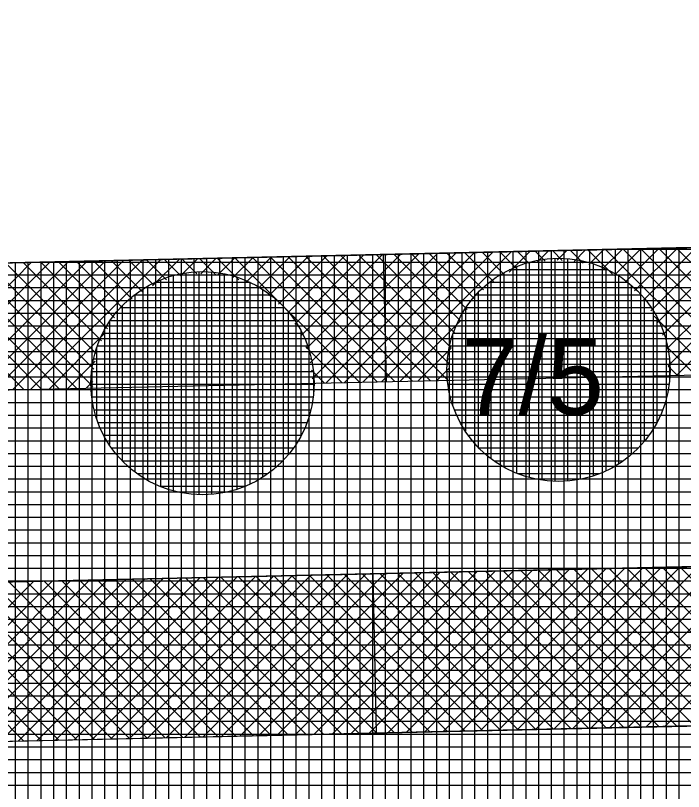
# Model space of a CAD drawing. Extents: x -566461 to -565198, y -1096301 to -1095707.
# Drawn here: x -565625.26 to -565614.79, y -1095879.91 to -1095867.74 of the extents above; entities that cross this region are included whole.
import ezdxf

# ---------------------------------------------------------------- set-up
doc = ezdxf.new("R2010")
doc.units = 0
for name, color, linetype in [('Vrstva 13', 7, 'Continuous'), ('Vrstva 40', 7, 'Continuous'), ('Vrstva 41', 7, 'Continuous'), ('Vrstva 42', 7, 'Continuous'), ('Vrstva 43', 7, 'Continuous'), ('Vrstva 44', 7, 'Continuous')]:
    doc.layers.add(name, color=color, linetype=linetype)

msp = doc.modelspace()

# ---------------------------------------------------------------- linework, layer by layer
at = {"layer": 'Vrstva 13'}
for p, q in [((-565630.22, -1095871.73), (-565610.5, -1095871.29)), ((-565630.41, -1095876.736), (-565610.165, -1095876.284)), ((-565630.354, -1095879.235), (-565610.109, -1095878.783))]:
    msp.add_line(p, q, dxfattribs=at)
at = {"layer": 'Vrstva 41'}
for p, q in [((-565615.422, -1095872.21), (-565614.593, -1095871.381)), ((-565615.303, -1095872.374), (-565614.304, -1095871.375)), ((-565615.201, -1095872.556), (-565614.014, -1095871.368)), ((-565615.119, -1095872.756), (-565613.725, -1095871.362)), ((-565615.062, -1095872.981), (-565613.436, -1095871.356)), ((-565615.033, -1095873.236), (-565613.146, -1095871.349)), ((-565614.901, -1095873.386), (-565612.857, -1095871.343)), ((-565621.004, -1095872.418), (-565620.09, -1095871.504)), ((-565620.885, -1095872.582), (-565619.8, -1095871.498)), ((-565620.783, -1095872.763), (-565619.511, -1095871.491)), ((-565620.7, -1095872.963), (-565619.222, -1095871.485)), ((-565620.642, -1095873.188), (-565618.932, -1095871.478)), ((-565620.614, -1095873.442), (-565618.643, -1095871.472)), ((-565620.393, -1095873.505), (-565618.354, -1095871.465)), ((-565618.465, -1095873.203), (-565620.162, -1095871.506)), ((-565620.104, -1095873.498), (-565618.065, -1095871.459)), ((-565618.434, -1095872.952), (-565619.886, -1095871.499)), ((-565619.815, -1095873.492), (-565617.775, -1095871.452)), ((-565618.372, -1095872.731), (-565619.609, -1095871.493)), ((-565619.526, -1095873.486), (-565617.486, -1095871.446)), ((-565618.287, -1095872.533), (-565619.332, -1095871.487)), ((-565618.184, -1095872.353), (-565619.056, -1095871.481)), ((-565618.062, -1095872.191), (-565618.779, -1095871.475)), ((-565617.925, -1095872.046), (-565618.502, -1095871.469)), ((-565617.772, -1095871.917), (-565618.226, -1095871.462)), ((-565617.6, -1095871.805), (-565617.949, -1095871.456)), ((-565617.409, -1095871.713), (-565617.672, -1095871.45)), ((-565617.523, -1095871.766), (-565617.197, -1095871.439)), ((-565617.198, -1095871.642), (-565617.396, -1095871.444)), ((-565616.962, -1095871.594), (-565617.119, -1095871.438)), ((-565617.089, -1095871.615), (-565616.907, -1095871.433)), ((-565616.691, -1095871.583), (-565616.842, -1095871.432)), ((-565616.773, -1095871.581), (-565616.618, -1095871.427)), ((-565616.366, -1095871.625), (-565616.566, -1095871.425)), ((-565616.508, -1095871.599), (-565616.329, -1095871.42)), ((-565615.907, -1095871.802), (-565616.289, -1095871.419)), ((-565616.275, -1095871.649), (-565616.039, -1095871.414)), ((-565616.066, -1095871.723), (-565615.75, -1095871.407)), ((-565614.058, -1095873.368), (-565616.012, -1095871.413)), ((-565615.878, -1095871.818), (-565615.461, -1095871.401)), ((-565613.781, -1095873.362), (-565615.736, -1095871.407)), ((-565615.709, -1095871.932), (-565615.172, -1095871.394)), ((-565615.558, -1095872.063), (-565614.882, -1095871.388)), ((-565613.681, -1095873.178), (-565615.459, -1095871.401)), ((-565613.658, -1095872.919), (-565615.182, -1095871.394)), ((-565613.605, -1095872.689), (-565614.906, -1095871.388)), ((-565626.13, -1095872.736), (-565625.008, -1095871.614)), ((-565626.04, -1095872.928), (-565624.718, -1095871.607)), ((-565625.97, -1095873.141), (-565624.429, -1095871.601)), ((-565625.925, -1095873.379), (-565624.14, -1095871.594)), ((-565625.886, -1095873.623), (-565623.85, -1095871.588)), ((-565625.597, -1095873.617), (-565623.561, -1095871.581)), ((-565623.986, -1095873.056), (-565625.419, -1095871.623)), ((-565625.308, -1095873.611), (-565623.272, -1095871.575)), ((-565623.914, -1095872.845), (-565625.142, -1095871.617)), ((-565625.019, -1095873.604), (-565622.983, -1095871.569)), ((-565623.821, -1095872.655), (-565624.866, -1095871.611)), ((-565623.709, -1095872.484), (-565624.589, -1095871.604)), ((-565623.58, -1095872.331), (-565624.312, -1095871.598)), ((-565623.434, -1095872.194), (-565624.036, -1095871.592)), ((-565623.271, -1095872.074), (-565623.759, -1095871.586)), ((-565623.092, -1095871.971), (-565623.482, -1095871.58)), ((-565622.893, -1095871.886), (-565623.206, -1095871.573)), ((-565623.113, -1095871.981), (-565622.693, -1095871.562)), ((-565622.671, -1095871.825), (-565622.929, -1095871.567)), ((-565622.674, -1095871.826), (-565622.404, -1095871.556)), ((-565622.419, -1095871.795), (-565622.652, -1095871.561)), ((-565622.127, -1095871.804), (-565622.376, -1095871.555)), ((-565622.357, -1095871.792), (-565622.115, -1095871.549)), ((-565621.758, -1095871.89), (-565622.099, -1095871.549)), ((-565622.092, -1095871.809), (-565621.825, -1095871.543)), ((-565621.858, -1095871.858), (-565621.536, -1095871.536)), ((-565619.872, -1095873.493), (-565621.822, -1095871.543)), ((-565621.649, -1095871.932), (-565621.247, -1095871.53)), ((-565619.595, -1095873.487), (-565621.546, -1095871.536)), ((-565621.461, -1095872.027), (-565620.958, -1095871.523)), ((-565621.292, -1095872.141), (-565620.668, -1095871.517)), ((-565619.318, -1095873.481), (-565621.269, -1095871.53)), ((-565621.14, -1095872.271), (-565620.379, -1095871.51)), ((-565619.041, -1095873.475), (-565620.992, -1095871.524)), ((-565618.764, -1095873.469), (-565620.716, -1095871.518)), ((-565618.487, -1095873.463), (-565620.439, -1095871.512)), ((-565625.132, -1095873.607), (-565627.079, -1095871.66)), ((-565624.855, -1095873.601), (-565626.802, -1095871.654)), ((-565624.578, -1095873.595), (-565626.526, -1095871.648)), ((-565624.302, -1095873.589), (-565626.249, -1095871.641)), ((-565624.047, -1095873.56), (-565625.972, -1095871.635)), ((-565624.034, -1095873.291), (-565625.696, -1095871.629)), ((-565614.334, -1095873.374), (-565615.252, -1095872.457)), ((-565619.237, -1095873.48), (-565618.284, -1095872.527)), ((-565624.729, -1095873.598), (-565623.859, -1095872.727)), ((-565620.149, -1095873.499), (-565620.71, -1095872.938)), ((-565618.948, -1095873.473), (-565618.435, -1095872.961)), ((-565614.611, -1095873.38), (-565615.075, -1095872.916)), ((-565624.44, -1095873.592), (-565624.014, -1095873.166)), ((-565620.425, -1095873.505), (-565620.624, -1095873.307)), ((-565618.659, -1095873.467), (-565618.469, -1095873.277)), ((-565614.888, -1095873.386), (-565615.033, -1095873.241)), ((-565624.151, -1095873.586), (-565624.048, -1095873.483)), ((-565616.528, -1095878.92), (-565613.977, -1095876.369)), ((-565616.238, -1095878.913), (-565613.688, -1095876.363)), ((-565615.949, -1095878.906), (-565613.399, -1095876.356)), ((-565615.66, -1095878.9), (-565613.11, -1095876.35)), ((-565615.37, -1095878.893), (-565612.82, -1095876.343)), ((-565615.081, -1095878.887), (-565612.531, -1095876.337)), ((-565622.027, -1095879.045), (-565619.474, -1095876.492)), ((-565621.738, -1095879.038), (-565619.185, -1095876.485)), ((-565621.448, -1095879.032), (-565618.896, -1095876.479)), ((-565621.159, -1095879.025), (-565618.606, -1095876.472)), ((-565620.87, -1095879.019), (-565618.317, -1095876.466)), ((-565620.58, -1095879.012), (-565618.028, -1095876.46)), ((-565620.291, -1095879.005), (-565617.738, -1095876.453)), ((-565620.001, -1095878.999), (-565617.449, -1095876.447)), ((-565619.712, -1095878.992), (-565617.16, -1095876.44)), ((-565617.113, -1095878.933), (-565619.553, -1095876.494)), ((-565619.422, -1095878.986), (-565616.87, -1095876.434)), ((-565616.837, -1095878.927), (-565619.276, -1095876.487)), ((-565619.133, -1095878.979), (-565616.581, -1095876.427)), ((-565616.56, -1095878.92), (-565618.999, -1095876.481)), ((-565618.843, -1095878.972), (-565616.292, -1095876.421)), ((-565616.284, -1095878.914), (-565618.723, -1095876.475)), ((-565618.554, -1095878.966), (-565616.003, -1095876.414)), ((-565616.007, -1095878.908), (-565618.446, -1095876.469)), ((-565618.265, -1095878.959), (-565615.713, -1095876.408)), ((-565615.731, -1095878.901), (-565618.169, -1095876.463)), ((-565617.975, -1095878.953), (-565615.424, -1095876.401)), ((-565615.454, -1095878.895), (-565617.893, -1095876.457)), ((-565617.686, -1095878.946), (-565615.135, -1095876.395)), ((-565615.178, -1095878.889), (-565617.616, -1095876.45)), ((-565617.396, -1095878.939), (-565614.845, -1095876.388)), ((-565614.901, -1095878.882), (-565617.339, -1095876.444)), ((-565617.107, -1095878.933), (-565614.556, -1095876.382)), ((-565614.625, -1095878.876), (-565617.063, -1095876.438)), ((-565616.817, -1095878.926), (-565614.267, -1095876.376)), ((-565614.348, -1095878.87), (-565616.786, -1095876.432)), ((-565614.072, -1095878.863), (-565616.509, -1095876.426)), ((-565613.795, -1095878.857), (-565616.233, -1095876.419)), ((-565613.518, -1095878.851), (-565615.956, -1095876.413)), ((-565613.242, -1095878.845), (-565615.679, -1095876.407)), ((-565612.965, -1095878.838), (-565615.403, -1095876.401)), ((-565612.689, -1095878.832), (-565615.126, -1095876.395)), ((-565612.412, -1095878.826), (-565614.849, -1095876.389)), ((-565627.527, -1095879.17), (-565624.971, -1095876.615)), ((-565627.237, -1095879.164), (-565624.682, -1095876.608)), ((-565626.948, -1095879.157), (-565624.392, -1095876.602)), ((-565626.659, -1095879.151), (-565624.103, -1095876.595)), ((-565626.369, -1095879.144), (-565623.814, -1095876.589)), ((-565626.08, -1095879.137), (-565623.524, -1095876.582)), ((-565625.79, -1095879.131), (-565623.235, -1095876.576)), ((-565625.501, -1095879.124), (-565622.946, -1095876.569)), ((-565625.211, -1095879.118), (-565622.656, -1095876.563)), ((-565624.922, -1095879.111), (-565622.367, -1095876.556)), ((-565622.368, -1095879.053), (-565624.809, -1095876.611)), ((-565624.632, -1095879.104), (-565622.078, -1095876.55)), ((-565622.091, -1095879.046), (-565624.533, -1095876.605)), ((-565624.343, -1095879.098), (-565621.789, -1095876.544)), ((-565621.814, -1095879.04), (-565624.256, -1095876.599)), ((-565624.053, -1095879.091), (-565621.499, -1095876.537)), ((-565621.538, -1095879.034), (-565623.979, -1095876.592)), ((-565623.764, -1095879.085), (-565621.21, -1095876.531)), ((-565621.261, -1095879.028), (-565623.703, -1095876.586)), ((-565623.475, -1095879.078), (-565620.921, -1095876.524)), ((-565620.985, -1095879.021), (-565623.426, -1095876.58)), ((-565623.185, -1095879.071), (-565620.631, -1095876.518)), ((-565620.708, -1095879.015), (-565623.149, -1095876.574)), ((-565622.896, -1095879.065), (-565620.342, -1095876.511)), ((-565620.432, -1095879.009), (-565622.873, -1095876.568)), ((-565622.606, -1095879.058), (-565620.053, -1095876.505)), ((-565620.155, -1095879.002), (-565622.596, -1095876.562)), ((-565619.879, -1095878.996), (-565622.319, -1095876.555)), ((-565622.317, -1095879.052), (-565619.763, -1095876.498)), ((-565619.602, -1095878.99), (-565622.043, -1095876.549)), ((-565619.326, -1095878.983), (-565621.766, -1095876.543)), ((-565619.049, -1095878.977), (-565621.489, -1095876.537)), ((-565618.773, -1095878.971), (-565621.213, -1095876.531)), ((-565618.496, -1095878.964), (-565620.936, -1095876.524)), ((-565618.22, -1095878.958), (-565620.659, -1095876.518)), ((-565617.943, -1095878.952), (-565620.383, -1095876.512)), ((-565617.666, -1095878.946), (-565620.106, -1095876.506)), ((-565617.39, -1095878.939), (-565619.829, -1095876.5)), ((-565625.133, -1095879.116), (-565627.576, -1095876.673)), ((-565624.856, -1095879.11), (-565627.299, -1095876.667)), ((-565624.58, -1095879.103), (-565627.023, -1095876.66)), ((-565624.303, -1095879.097), (-565626.746, -1095876.654)), ((-565624.027, -1095879.091), (-565626.469, -1095876.648)), ((-565623.75, -1095879.084), (-565626.193, -1095876.642)), ((-565623.474, -1095879.078), (-565625.916, -1095876.636)), ((-565623.197, -1095879.072), (-565625.639, -1095876.629)), ((-565622.921, -1095879.065), (-565625.363, -1095876.623)), ((-565622.644, -1095879.059), (-565625.086, -1095876.617))]:
    msp.add_line(p, q, dxfattribs=at)
at = {"layer": 'Vrstva 42'}
for p, q in [((-565619.498, -1095871.491), (-565619.453, -1095873.484)), ((-565619.663, -1095876.496), (-565619.607, -1095878.995))]:
    msp.add_line(p, q, dxfattribs=at)
for points in [[(-565642.21, -1095870.56), (-565642.251, -1095872.566), (-565630.414, -1095873.721), (-565610.455, -1095873.29), (-565587.747, -1095870.748), (-565569.297, -1095867.734), (-565519.622, -1095865.105), (-565519.36, -1095863.08), (-565569.62, -1095865.76), (-565587.97, -1095868.76), (-565610.5, -1095871.29), (-565630.22, -1095871.73)], [(-565642.542, -1095875.552), (-565642.365, -1095878.081), (-565630.354, -1095879.235), (-565609.886, -1095878.768), (-565587.002, -1095876.198), (-565568.675, -1095873.205), (-565520.341, -1095870.651), (-565520.014, -1095868.13), (-565569.078, -1095870.738), (-565587.281, -1095873.714), (-565610.165, -1095876.284), (-565630.41, -1095876.736)]]:
    msp.add_lwpolyline(points, close=True, dxfattribs=at)
at = {"layer": 'Vrstva 43'}
for p, q in [((-565620.06, -1095886.508), (-565620.06, -1095871.503)), ((-565619.86, -1095886.504), (-565619.86, -1095871.499)), ((-565619.66, -1095886.499), (-565619.66, -1095871.494)), ((-565619.46, -1095886.495), (-565619.46, -1095871.49)), ((-565619.26, -1095886.49), (-565619.26, -1095871.485)), ((-565619.06, -1095886.486), (-565619.06, -1095871.481)), ((-565618.86, -1095886.481), (-565618.86, -1095871.477)), ((-565618.66, -1095886.477), (-565618.66, -1095871.472)), ((-565618.46, -1095886.472), (-565618.46, -1095871.468)), ((-565618.26, -1095886.468), (-565618.26, -1095871.463)), ((-565618.06, -1095886.463), (-565618.06, -1095871.459)), ((-565617.86, -1095886.459), (-565617.86, -1095871.454)), ((-565617.66, -1095886.454), (-565617.66, -1095871.45)), ((-565617.46, -1095886.45), (-565617.46, -1095871.445)), ((-565617.26, -1095886.445), (-565617.26, -1095871.441)), ((-565617.06, -1095886.441), (-565617.06, -1095871.436)), ((-565616.86, -1095886.436), (-565616.86, -1095871.432)), ((-565616.66, -1095886.432), (-565616.66, -1095871.427)), ((-565616.46, -1095886.427), (-565616.46, -1095871.423)), ((-565616.26, -1095886.423), (-565616.26, -1095871.419)), ((-565616.06, -1095886.418), (-565616.06, -1095871.414)), ((-565615.878, -1095871.41), (-565520.439, -1095871.41)), ((-565615.86, -1095886.414), (-565615.86, -1095871.41)), ((-565615.66, -1095886.409), (-565615.66, -1095871.405)), ((-565615.46, -1095886.405), (-565615.46, -1095871.401)), ((-565615.26, -1095886.4), (-565615.26, -1095871.396)), ((-565615.06, -1095886.396), (-565615.06, -1095871.392)), ((-565614.86, -1095886.391), (-565614.86, -1095871.387)), ((-565625.26, -1095886.626), (-565625.26, -1095871.619)), ((-565625.06, -1095886.621), (-565625.06, -1095871.615)), ((-565624.86, -1095886.617), (-565624.86, -1095871.61)), ((-565624.842, -1095871.61), (-565520.465, -1095871.61)), ((-565624.66, -1095886.612), (-565624.66, -1095871.606)), ((-565624.46, -1095886.608), (-565624.46, -1095871.601)), ((-565624.26, -1095886.603), (-565624.26, -1095871.597)), ((-565624.06, -1095886.598), (-565624.06, -1095871.593)), ((-565623.86, -1095886.594), (-565623.86, -1095871.588)), ((-565623.66, -1095886.589), (-565623.66, -1095871.584)), ((-565623.46, -1095886.585), (-565623.46, -1095871.579)), ((-565623.26, -1095886.58), (-565623.26, -1095871.575)), ((-565623.06, -1095886.576), (-565623.06, -1095871.57)), ((-565622.86, -1095886.571), (-565622.86, -1095871.566)), ((-565622.66, -1095886.567), (-565622.66, -1095871.561)), ((-565622.46, -1095886.562), (-565622.46, -1095871.557)), ((-565622.26, -1095886.558), (-565622.26, -1095871.552)), ((-565622.06, -1095886.553), (-565622.06, -1095871.548)), ((-565621.86, -1095886.549), (-565621.86, -1095871.543)), ((-565621.66, -1095886.544), (-565621.66, -1095871.539)), ((-565621.46, -1095886.54), (-565621.46, -1095871.535)), ((-565621.26, -1095886.535), (-565621.26, -1095871.53)), ((-565621.06, -1095886.531), (-565621.06, -1095871.526)), ((-565620.86, -1095886.526), (-565620.86, -1095871.521)), ((-565620.66, -1095886.522), (-565620.66, -1095871.517)), ((-565620.46, -1095886.517), (-565620.46, -1095871.512)), ((-565620.26, -1095886.513), (-565620.26, -1095871.508)), ((-565642.236, -1095871.81), (-565520.491, -1095871.81)), ((-565642.24, -1095872.01), (-565520.517, -1095872.01)), ((-565642.244, -1095872.21), (-565520.543, -1095872.21)), ((-565642.248, -1095872.41), (-565520.569, -1095872.41)), ((-565642.252, -1095872.61), (-565520.595, -1095872.61)), ((-565642.256, -1095872.81), (-565520.62, -1095872.81)), ((-565642.26, -1095873.01), (-565520.646, -1095873.01)), ((-565642.265, -1095873.21), (-565520.672, -1095873.21)), ((-565642.269, -1095873.41), (-565520.698, -1095873.41)), ((-565642.273, -1095873.61), (-565520.724, -1095873.61)), ((-565642.277, -1095873.81), (-565520.75, -1095873.81)), ((-565642.281, -1095874.01), (-565520.776, -1095874.01)), ((-565642.285, -1095874.21), (-565520.802, -1095874.21)), ((-565642.289, -1095874.41), (-565520.828, -1095874.41)), ((-565642.293, -1095874.61), (-565520.854, -1095874.61)), ((-565642.298, -1095874.81), (-565520.88, -1095874.81)), ((-565642.302, -1095875.01), (-565520.905, -1095875.01)), ((-565642.306, -1095875.21), (-565520.931, -1095875.21)), ((-565642.31, -1095875.41), (-565520.957, -1095875.41)), ((-565642.314, -1095875.61), (-565520.983, -1095875.61)), ((-565642.318, -1095875.81), (-565521.009, -1095875.81)), ((-565642.322, -1095876.01), (-565521.035, -1095876.01)), ((-565642.326, -1095876.21), (-565521.061, -1095876.21)), ((-565642.331, -1095876.41), (-565521.087, -1095876.41)), ((-565642.335, -1095876.61), (-565521.113, -1095876.61)), ((-565642.339, -1095876.81), (-565521.139, -1095876.81)), ((-565642.343, -1095877.01), (-565521.165, -1095877.01)), ((-565642.347, -1095877.21), (-565521.19, -1095877.21)), ((-565642.351, -1095877.41), (-565521.216, -1095877.41)), ((-565642.355, -1095877.61), (-565521.242, -1095877.61)), ((-565642.359, -1095877.81), (-565521.268, -1095877.81)), ((-565642.364, -1095878.01), (-565521.294, -1095878.01)), ((-565642.368, -1095878.21), (-565521.32, -1095878.21)), ((-565642.372, -1095878.41), (-565525.085, -1095878.41)), ((-565642.376, -1095878.61), (-565528.851, -1095878.61)), ((-565642.38, -1095878.81), (-565532.616, -1095878.81)), ((-565642.384, -1095879.01), (-565536.381, -1095879.01)), ((-565642.388, -1095879.21), (-565540.147, -1095879.21)), ((-565642.392, -1095879.41), (-565543.912, -1095879.41)), ((-565642.397, -1095879.61), (-565547.677, -1095879.61)), ((-565642.401, -1095879.81), (-565551.443, -1095879.81))]:
    msp.add_line(p, q, dxfattribs=at)
msp.add_lwpolyline([(-565639.56, -1095885.89), (-565630.78, -1095886.75), (-565609.49, -1095886.27), (-565595.88, -1095884.74), (-565585.92, -1095883.62), (-565568.01, -1095880.69), (-565521.32, -1095878.21), (-565519.36, -1095863.08), (-565522.03, -1095863.23), (-565569.62, -1095865.76), (-565587.97, -1095868.76), (-565610.5, -1095871.29), (-565630.22, -1095871.73), (-565642.21, -1095870.56), (-565642.52, -1095885.6), (-565645.08, -1096008.78), (-565642.11, -1096010.51)], close=True, dxfattribs=at)
at = {"layer": 'Vrstva 44'}
for p, q in [((-565617.21, -1095871.612), (-565617.21, -1095874.988)), ((-565617.01, -1095871.571), (-565617.01, -1095875.029)), ((-565616.81, -1095871.553), (-565616.81, -1095875.048)), ((-565616.61, -1095871.557), (-565616.61, -1095875.043)), ((-565616.41, -1095871.584), (-565616.41, -1095875.015)), ((-565615.981, -1095871.73), (-565617.522, -1095871.73)), ((-565617.41, -1095871.681), (-565617.41, -1095874.92)), ((-565616.21, -1095871.636), (-565616.21, -1095874.963)), ((-565616.01, -1095871.716), (-565616.01, -1095874.885)), ((-565622.79, -1095871.822), (-565622.79, -1095875.198)), ((-565622.59, -1095871.781), (-565622.59, -1095875.239)), ((-565622.39, -1095871.763), (-565622.39, -1095875.258)), ((-565622.19, -1095871.767), (-565622.19, -1095875.253)), ((-565621.99, -1095871.794), (-565621.99, -1095875.225)), ((-565621.79, -1095871.846), (-565621.79, -1095875.173)), ((-565617.61, -1095871.778), (-565617.61, -1095874.822)), ((-565615.81, -1095871.825), (-565615.81, -1095874.774)), ((-565623.19, -1095871.988), (-565623.19, -1095875.032)), ((-565621.582, -1095871.93), (-565623.079, -1095871.93)), ((-565622.99, -1095871.891), (-565622.99, -1095875.13)), ((-565621.59, -1095871.926), (-565621.59, -1095875.095)), ((-565615.663, -1095871.93), (-565617.837, -1095871.93)), ((-565617.81, -1095871.908), (-565617.81, -1095874.691)), ((-565615.61, -1095871.974), (-565615.61, -1095874.626)), ((-565621.39, -1095872.035), (-565621.39, -1095874.984)), ((-565618.01, -1095872.088), (-565618.01, -1095874.512)), ((-565621.256, -1095872.13), (-565623.405, -1095872.13)), ((-565623.39, -1095872.118), (-565623.39, -1095874.901)), ((-565621.19, -1095872.184), (-565621.19, -1095874.836)), ((-565615.451, -1095872.13), (-565618.051, -1095872.13)), ((-565615.41, -1095872.175), (-565615.41, -1095874.423)), ((-565621.04, -1095872.33), (-565623.621, -1095872.33)), ((-565623.59, -1095872.298), (-565623.59, -1095874.722)), ((-565618.21, -1095872.339), (-565618.21, -1095874.262)), ((-565615.295, -1095872.33), (-565618.204, -1095872.33)), ((-565620.99, -1095872.385), (-565620.99, -1095874.633)), ((-565615.21, -1095872.47), (-565615.21, -1095874.127)), ((-565623.79, -1095872.549), (-565623.79, -1095874.472)), ((-565620.881, -1095872.53), (-565623.778, -1095872.53)), ((-565615.181, -1095872.53), (-565618.32, -1095872.53)), ((-565620.79, -1095872.68), (-565620.79, -1095874.337)), ((-565620.766, -1095872.73), (-565623.895, -1095872.73)), ((-565618.41, -1095872.751), (-565618.41, -1095873.852)), ((-565615.097, -1095872.73), (-565618.404, -1095872.73)), ((-565623.99, -1095872.961), (-565623.99, -1095874.062)), ((-565620.681, -1095872.93), (-565623.981, -1095872.93)), ((-565615.04, -1095872.93), (-565618.459, -1095872.93)), ((-565620.622, -1095873.13), (-565624.037, -1095873.13)), ((-565615.01, -1095873.13), (-565618.49, -1095873.13)), ((-565615.01, -1095873.128), (-565615.01, -1095873.47)), ((-565620.591, -1095873.33), (-565624.069, -1095873.33)), ((-565615.002, -1095873.33), (-565618.498, -1095873.33)), ((-565620.59, -1095873.338), (-565620.59, -1095873.68)), ((-565620.582, -1095873.53), (-565624.078, -1095873.53)), ((-565615.017, -1095873.53), (-565618.484, -1095873.53)), ((-565620.596, -1095873.73), (-565624.065, -1095873.73)), ((-565615.055, -1095873.73), (-565618.445, -1095873.73)), ((-565620.632, -1095873.93), (-565624.028, -1095873.93)), ((-565615.118, -1095873.93), (-565618.381, -1095873.93)), ((-565620.694, -1095874.13), (-565623.965, -1095874.13)), ((-565615.212, -1095874.13), (-565618.289, -1095874.13)), ((-565620.786, -1095874.33), (-565623.874, -1095874.33)), ((-565615.336, -1095874.33), (-565618.163, -1095874.33)), ((-565620.91, -1095874.53), (-565623.751, -1095874.53)), ((-565615.508, -1095874.53), (-565617.993, -1095874.53)), ((-565621.078, -1095874.73), (-565623.582, -1095874.73)), ((-565615.744, -1095874.73), (-565617.755, -1095874.73)), ((-565621.309, -1095874.93), (-565623.349, -1095874.93)), ((-565616.116, -1095874.93), (-565617.385, -1095874.93)), ((-565621.673, -1095875.13), (-565622.991, -1095875.13))]:
    msp.add_line(p, q, dxfattribs=at)
for centre in [(-565616.75, -1095873.3), (-565622.33, -1095873.51)]:
    msp.add_circle(centre, 1.75, dxfattribs=at)

# ---------------------------------------------------------------- texts
at = {"layer": 'Vrstva 40'}
msp.add_text('7/5', height=1.2, dxfattribs=at).set_placement((-565618.27, -1095874))

doc.saveas('drawing.dxf')
